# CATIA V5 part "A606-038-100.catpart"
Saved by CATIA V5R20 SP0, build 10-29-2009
Part number: A606-038-100
Source: Unknown
Property "ARTICLENO": "A606-038-100"
Property "BOMINFO": "A606-038-100"
Property "CODE": "A606-038-100"
Property "HOLES": "2"
Property "L": "100.000"
Property "L1": "25.000"
Property "L2": "50.000"
Property "LINA": "A606-038-100"
Property "NB": "A606-038-100"
Property "NBSYN": "$CODE."
Property "NN": "A606"
Property "NT": "Wear Plates, self-lubricating"
Property "SCREW": "2xM6"
Property "SUPPLIER": "CF"
Property "W": "38.000"
Bounding box of the stored display mesh (mm): x -19 to 19, y -5 to 5, z -50 to 50
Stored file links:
  C:\Users\Utente\Desktop\3D files A606\A606-038-100.catpart
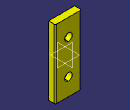
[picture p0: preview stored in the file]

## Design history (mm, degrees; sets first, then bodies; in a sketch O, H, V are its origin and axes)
Body1 "Geometry.1" (main body)
  Solid1 "A606-038-100.catpart": solid without history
